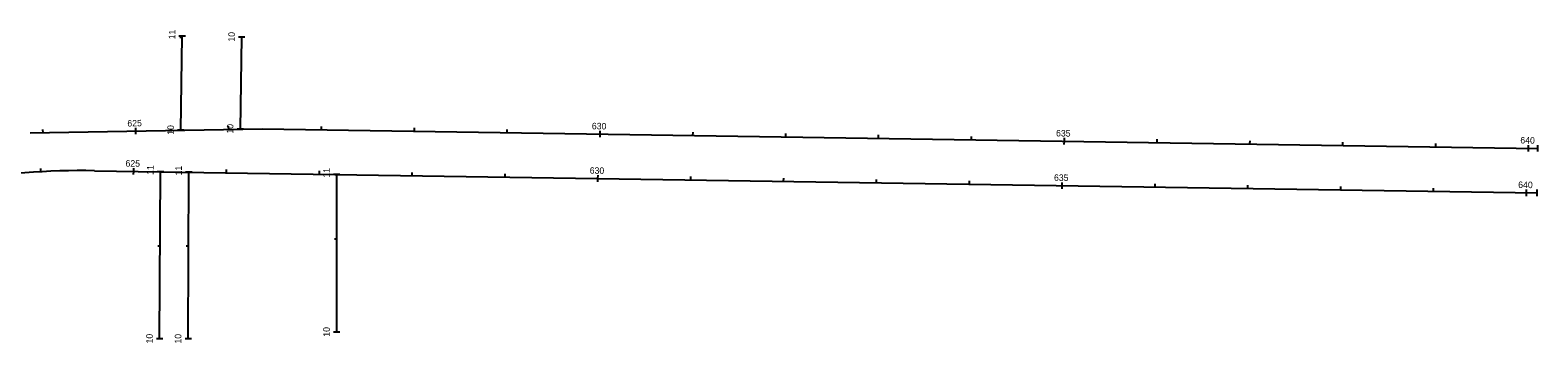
# Model space of a CAD drawing. Extents: x 596008 to 607538, y 326212 to 405053.
# Drawn here: x 604538 to 606161, y 349720 to 350057 of the extents above; entities that cross this region are included whole.
import ezdxf

# ---------------------------------------------------------------- set-up
doc = ezdxf.new("R2010")
doc.units = 0
for name, color, linetype in [('P_ALI', 7, 'Continuous'), ('P_ALI_200_Sta', 7, 'Continuous'), ('P_ALI_200_Tic', 7, 'Continuous')]:
    doc.layers.add(name, color=color, linetype=linetype)

msp = doc.modelspace()

# ---------------------------------------------------------------- linework, layer by layer
at = {"layer": 'P_ALI'}
for points in [[(604700.1, 349948.9), (604701.6, 350050.3)], [(604764.2, 349950.1), (604765.7, 350049.3)], [(604537.9, 349946), (604787.8, 349950.5)], [(604787.8, 349950.5), (606161.4, 349929.4)], [(604607.3, 349905.3), (606160.7, 349881.4)], [(604677.3, 349724), (604678.2, 349904.2)], [(604708.2, 349723.9), (604708.7, 349903.7)], [(604868, 349731.3), (604868, 349901.3)]]:
    msp.add_lwpolyline(points, dxfattribs=at)
msp.add_arc((604595, 349105.4), 800, 89.1186, 99.8942, dxfattribs=at)
at = {"layer": 'P_ALI_200_Sta'}
for points in [[(604701.6, 350050.3), (604698.1, 350050.4)], [(604701.6, 350050.3), (604701.6, 350050.3)], [(604705.1, 350050.3), (604701.6, 350050.3)], [(604765.7, 350049.3), (604762.2, 350049.4)], [(604765.7, 350049.3), (604765.7, 350049.3)], [(604769.2, 350049.3), (604765.7, 350049.3)], [(604551.7, 349946.3), (604551.6, 349949.8)], [(604651.7, 349948.1), (604651.6, 349951.6)], [(604651.7, 349948.1), (604651.7, 349948.1)], [(604651.7, 349944.6), (604651.7, 349948.1)], [(604700.1, 349948.9), (604696.6, 349949)], [(604700.1, 349948.9), (604700.1, 349948.9)], [(604703.6, 349948.9), (604700.1, 349948.9)], [(604751.7, 349949.9), (604751.6, 349953.4)], [(604764.2, 349950.1), (604760.7, 349950.1)], [(604764.2, 349950.1), (604764.2, 349950.1)], [(604767.7, 349950), (604764.2, 349950.1)], [(604851.7, 349949.5), (604851.7, 349953)], [(604951.6, 349948), (604951.7, 349951.5)], [(605051.6, 349946.4), (605051.7, 349949.9)], [(605151.6, 349944.9), (605151.7, 349948.4)], [(605151.6, 349944.9), (605151.6, 349944.9)], [(605151.6, 349941.4), (605151.6, 349944.9)], [(605251.6, 349943.4), (605251.7, 349946.9)], [(605351.6, 349941.8), (605351.6, 349945.3)], [(605451.6, 349940.3), (605451.6, 349943.8)], [(605551.6, 349938.7), (605551.6, 349942.2)], [(605651.5, 349933.7), (605651.6, 349937.2)], [(605651.6, 349937.2), (605651.6, 349940.7)], [(605651.6, 349937.2), (605651.6, 349937.2)], [(605751.5, 349935.7), (605751.6, 349939.2)], [(605851.5, 349934.1), (605851.6, 349937.6)], [(605951.5, 349932.6), (605951.6, 349936.1)], [(606051.5, 349931.1), (606051.6, 349934.6)], [(606151.4, 349926), (606151.5, 349929.5)], [(606151.5, 349929.5), (606151.6, 349933)], [(606151.5, 349929.5), (606151.5, 349929.5)], [(606161.4, 349929.4), (606161.5, 349932.9)], [(606161.4, 349929.4), (606161.4, 349929.4)], [(606161.4, 349925.9), (606161.4, 349929.4)], [(604549.4, 349904.1), (604549.2, 349907.6)], [(604649.3, 349901.1), (604649.4, 349904.6)], [(604649.4, 349904.6), (604649.4, 349908.1)], [(604649.4, 349904.6), (604649.4, 349904.6)], [(604678.2, 349904.2), (604674.7, 349904.2)], [(604678.2, 349904.2), (604678.2, 349904.2)], [(604681.7, 349904.2), (604678.2, 349904.2)], [(604708.7, 349903.7), (604705.2, 349903.7)], [(604708.7, 349903.7), (604708.7, 349903.7)], [(604712.2, 349903.7), (604708.7, 349903.7)], [(604749.4, 349903.1), (604749.4, 349906.6)], [(604849.4, 349901.5), (604849.4, 349905)], [(604868, 349901.3), (604864.5, 349901.3)], [(604868, 349901.3), (604868, 349901.3)], [(604871.5, 349901.3), (604868, 349901.3)], [(604949.4, 349900), (604949.4, 349903.5)], [(605049.3, 349898.5), (605049.4, 349902)], [(605149.3, 349896.9), (605149.4, 349900.4)], [(605149.3, 349896.9), (605149.3, 349896.9)], [(605149.3, 349893.4), (605149.3, 349896.9)], [(605249.3, 349895.4), (605249.4, 349898.9)], [(605349.3, 349893.9), (605349.4, 349897.4)], [(605449.3, 349892.3), (605449.4, 349895.8)], [(605549.3, 349890.8), (605549.3, 349894.3)], [(605649.2, 349885.7), (605649.3, 349889.2)], [(605649.3, 349889.2), (605649.3, 349892.7)], [(605649.3, 349889.2), (605649.3, 349889.2)], [(605749.3, 349887.7), (605749.3, 349891.2)], [(605849.3, 349886.2), (605849.3, 349889.7)], [(605949.2, 349884.6), (605949.3, 349888.1)], [(606049.2, 349883.1), (606049.3, 349886.6)], [(606149.2, 349881.5), (606149.3, 349885)], [(606149.2, 349881.5), (606149.2, 349881.5)], [(606149.2, 349878), (606149.2, 349881.5)], [(606160.6, 349877.9), (606160.7, 349881.4)], [(606160.7, 349881.4), (606160.7, 349884.9)], [(606160.7, 349881.4), (606160.7, 349881.4)], [(604677.3, 349724), (604673.8, 349724)], [(604677.3, 349724), (604677.3, 349724)], [(604680.8, 349724), (604677.3, 349724)], [(604708.2, 349723.9), (604704.7, 349723.9)], [(604708.2, 349723.9), (604708.2, 349723.9)], [(604711.7, 349723.9), (604708.2, 349723.9)], [(604868, 349731.3), (604864.5, 349731.3)], [(604868, 349731.3), (604868, 349731.3)], [(604871.5, 349731.3), (604868, 349731.3)]]:
    msp.add_lwpolyline(points, dxfattribs=at)
at = {"layer": 'P_ALI_200_Tic'}
for points in [[(604701.6, 350048.9), (604699.1, 350048.9)], [(604868, 349831.3), (604865.5, 349831.3)], [(604677.8, 349824), (604675.3, 349824)], [(604708.5, 349823.9), (604706, 349823.9)]]:
    msp.add_lwpolyline(points, dxfattribs=at)

# ---------------------------------------------------------------- texts
at = {"layer": 'P_ALI_200_Sta'}
for s, height, rotation, p in [('11', 7, 89.1186, (604694.1, 350046.9)), ('10', 7, 89.1186, (604758.1, 350044.4)), ('625', 7, 1.0298, (604642.6, 349952.9)), ('10', 7, 89.1186, (604692.5, 349944)), ('10', 7, 89.1186, (604756.6, 349945.2)), ('630', 7, 359.1186, (605142.7, 349950)), ('635', 7, 359.1186, (605642.6, 349942.3)), ('640', 7, 359.1186, (606142.6, 349934.7)), ('640', 0.0000000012, 359.1186, (606161.5, 349934.4)), ('625', 7, 359.1186, (604640.5, 349909.8)), ('11', 7, 89.714, (604670.7, 349900.7)), ('11', 7, 89.821, (604701.2, 349900.2)), ('11', 7, 90, (604860.5, 349897.8)), ('630', 7, 359.1186, (605140.4, 349902.1)), ('635', 7, 359.1186, (605640.4, 349894.4)), ('640', 7, 359.1186, (606140.3, 349886.7)), ('640', 0.0000000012, 359.1186, (606160.8, 349886.4)), ('10', 7, 90, (604860.5, 349726.3)), ('10', 7, 89.714, (604669.8, 349719)), ('10', 7, 89.821, (604700.6, 349718.9))]:
    msp.add_text(s, height=height, rotation=rotation, dxfattribs=at).set_placement(p)

doc.saveas('drawing.dxf')
